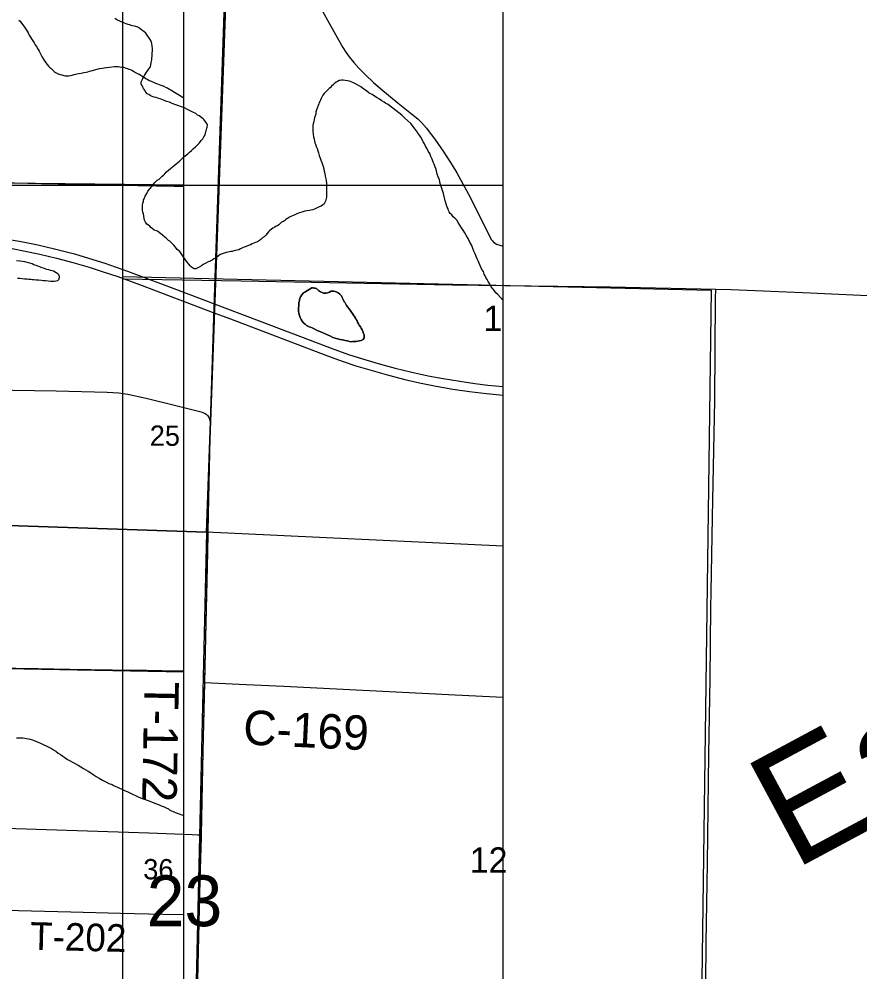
# Model space of a CAD drawing. Extents: x 0 to 68, y 0 to 52.9.
# Drawn here: x 49.292 to 51.122, y 35.551 to 37.625 of the extents above; entities that cross this region are included whole.
import ezdxf

# ---------------------------------------------------------------- set-up
doc = ezdxf.new("R2010")
doc.units = 0
for name, color, linetype in [('Default', 7, 'Continuous'), ('GM_X_County_Road', 7, 'Continuous'), ('GM_X_County_Road_Text', 7, 'Continuous'), ('GM_X_Minor_Lake', 7, 'Continuous'), ('GM_X_Minor_River', 7, 'Continuous'), ('GM_X_Minor_River_Text', 7, 'Continuous'), ('GM_X_State_Route', 7, 'Continuous'), ('GM_X_Township', 7, 'Continuous'), ('GM_X_Township_Road', 7, 'Continuous'), ('GM_X_Township_Road_Text', 7, 'Continuous')]:
    doc.layers.add(name, color=color, linetype=linetype)

msp = doc.modelspace()

# ---------------------------------------------------------------- linework, layer by layer
at = {"layer": 'Default'}
for p, q in [((49.5172, 34.4614), (49.5172, 52.9414)), ((50.3451, 32.7683), (50.3451, 42.0083)), ((49.6501, 31.1431), (49.6501, 38.5351)), ((41.1051, 37.2633), (50.3451, 37.2633))]:
    msp.add_line(p, q, dxfattribs=at)
for points in [[(48.4264, 37.8391), (49.7457, 37.7942), (49.6996, 36.5084), (48.3843, 36.5523)], [(48.3843, 36.5523), (49.6996, 36.5084), (49.6691, 35.1845), (48.3458, 35.227)]]:
    msp.add_lwpolyline(points, close=True, dxfattribs=at)
for points in [[(50.3451, 36.4776), (49.6996, 36.5084), (49.7457, 37.7942), (50.3451, 37.7786)], [(49.5419, 37.6098), (49.5384, 37.6108), (49.5354, 37.6113), (49.5324, 37.6123), (49.5289, 37.6133), (49.5244, 37.6149), (49.5214, 37.6164), (49.5179, 37.6179), (49.5139, 37.6194), (49.5094, 37.6214), (49.5059, 37.623), (49.5023, 37.625), (49.4998, 37.627)], [(49.5697, 37.2455), (49.5722, 37.2505), (49.5762, 37.2555), (49.5803, 37.261), (49.5868, 37.2695), (49.5923, 37.2745), (49.5964, 37.277), (49.6004, 37.28), (49.6034, 37.283), (49.6059, 37.2855), (49.6089, 37.2885), (49.6125, 37.2925), (49.6165, 37.296), (49.629, 37.3065), (49.6336, 37.31), (49.6371, 37.313), (49.6411, 37.316), (49.6436, 37.3185), (49.6466, 37.3215), (49.6502, 37.325), (49.6532, 37.3275), (49.6562, 37.3295), (49.6587, 37.332), (49.6617, 37.335), (49.6668, 37.339), (49.6708, 37.343), (49.6758, 37.347), (49.6798, 37.3515), (49.6844, 37.356), (49.6879, 37.3605), (49.6914, 37.3645), (49.6939, 37.369), (49.6959, 37.372), (49.6974, 37.3765), (49.698, 37.3795), (49.699, 37.382), (49.6995, 37.385), (49.7005, 37.3875), (49.701, 37.3901), (49.7015, 37.3941), (49.7, 37.3981), (49.698, 37.4011), (49.6945, 37.4056), (49.6925, 37.4081), (49.6895, 37.4102), (49.6865, 37.4122), (49.6835, 37.4142), (49.68, 37.4162), (49.676, 37.4197), (49.6695, 37.4228), (49.6639, 37.4253), (49.6579, 37.4283), (49.6514, 37.4319), (49.6309, 37.4394), (49.6248, 37.4415), (49.6188, 37.444), (49.6123, 37.446), (49.6063, 37.4486), (49.5988, 37.4516), (49.5938, 37.4531), (49.5898, 37.4541), (49.5857, 37.4551), (49.5812, 37.4567), (49.5772, 37.4587), (49.5737, 37.4607), (49.5707, 37.4627), (49.5672, 37.4662), (49.5647, 37.4713), (49.5627, 37.4738), (49.5612, 37.4768), (49.5592, 37.4803), (49.5577, 37.4833), (49.5577, 37.4883), (49.5597, 37.4928), (49.5607, 37.4959), (49.5628, 37.4994), (49.5648, 37.5024), (49.5668, 37.5059), (49.5688, 37.5094), (49.5718, 37.5134), (49.5743, 37.5169), (49.5774, 37.5209), (49.5784, 37.5254), (49.5794, 37.5309), (49.5799, 37.5339), (49.5804, 37.5364), (49.5809, 37.5404), (49.5814, 37.5455), (49.5814, 37.551), (49.582, 37.556), (49.582, 37.561), (49.5815, 37.566), (49.5805, 37.572), (49.5785, 37.5786), (49.5675, 37.5947), (49.5635, 37.5982), (49.559, 37.6012), (49.5545, 37.6047), (49.55, 37.6073), (49.546, 37.6088), (49.5419, 37.6098)], [(50.0654, 37.4571), (50.0599, 37.4611), (50.0539, 37.4642), (50.0479, 37.4687), (50.0419, 37.4727), (50.0354, 37.4778), (50.0253, 37.4838), (50.0178, 37.4873), (50.0108, 37.4899), (49.9973, 37.4924), (49.9932, 37.4919), (49.9907, 37.4914), (49.9882, 37.4915), (49.9847, 37.4895), (49.9817, 37.4875), (49.9792, 37.4855), (49.9757, 37.4825), (49.9716, 37.479), (49.9696, 37.4765), (49.9666, 37.474), (49.9641, 37.4715), (49.9616, 37.469), (49.9591, 37.4665), (49.9555, 37.463), (49.953, 37.4595), (49.9505, 37.4555), (49.949, 37.4525), (49.9475, 37.4489), (49.946, 37.4459), (49.945, 37.4434), (49.944, 37.4409), (49.9424, 37.4369), (49.9404, 37.4314), (49.9394, 37.4279), (49.9379, 37.4224), (49.9374, 37.4184), (49.9359, 37.4144), (49.9349, 37.4104), (49.9338, 37.4064), (49.9333, 37.4023), (49.9318, 37.3973), (49.9313, 37.3933), (49.9313, 37.3893), (49.9313, 37.3863), (49.9313, 37.3838), (49.9313, 37.3803), (49.9327, 37.3687), (49.9337, 37.3647), (49.9347, 37.3597), (49.9357, 37.3557), (49.9367, 37.3527), (49.9382, 37.3481), (49.9402, 37.3431), (49.9417, 37.3386), (49.9432, 37.3341), (49.9452, 37.3281), (49.9472, 37.3225), (49.9487, 37.318), (49.9507, 37.313), (49.9522, 37.3085), (49.9532, 37.304), (49.9547, 37.2994), (49.9557, 37.2939), (49.9571, 37.2889), (49.9581, 37.2834), (49.9591, 37.2773), (49.9601, 37.2728), (49.9606, 37.2678), (49.9611, 37.2638), (49.9611, 37.2588), (49.9611, 37.2538), (49.9611, 37.2487), (49.9606, 37.2447), (49.9611, 37.2417), (49.9605, 37.2377), (49.96, 37.2347), (49.9595, 37.2317), (49.9585, 37.2287), (49.957, 37.2262), (49.9555, 37.2232), (49.952, 37.2197), (49.949, 37.2182), (49.9449, 37.2162), (49.9404, 37.2142), (49.9359, 37.2122), (49.9314, 37.2102), (49.9269, 37.2092), (49.9238, 37.2087), (49.9183, 37.2077), (49.9138, 37.2068), (49.9093, 37.2058), (49.9002, 37.2028), (49.8962, 37.2013), (49.8917, 37.1993), (49.8867, 37.1968), (49.8832, 37.1953), (49.8802, 37.1938), (49.8756, 37.1908), (49.8726, 37.1888), (49.8691, 37.1858), (49.8656, 37.1838)], [(50.3451, 37.0128), (50.3338, 37.0253), (50.3298, 37.0293), (50.3263, 37.0334), (50.3238, 37.0369), (50.3213, 37.0394), (50.3188, 37.0434), (50.3173, 37.0464), (50.3158, 37.0494), (50.3128, 37.054), (50.3103, 37.058), (50.3078, 37.0625), (50.3063, 37.066), (50.3043, 37.0695), (50.3023, 37.0756), (50.2993, 37.0801), (50.2968, 37.0851), (50.2943, 37.0901), (50.2923, 37.0952), (50.2909, 37.0992), (50.2889, 37.1032), (50.2869, 37.1082), (50.2844, 37.1138), (50.2819, 37.1198), (50.2794, 37.1258), (50.2769, 37.1323), (50.2724, 37.1409), (50.2694, 37.1474), (50.2659, 37.1534), (50.2619, 37.1595), (50.2584, 37.1655), (50.2544, 37.171), (50.2509, 37.1766), (50.2474, 37.1821), (50.2444, 37.1876), (50.2404, 37.1917), (50.2369, 37.1947), (50.2339, 37.1987), (50.2299, 37.2022), (50.2279, 37.2057), (50.2264, 37.2083), (50.2254, 37.2118), (50.2234, 37.2158), (50.2219, 37.2203), (50.2204, 37.2248), (50.2194, 37.2293), (50.2154, 37.2454), (50.2124, 37.254), (50.2105, 37.2605), (50.2085, 37.2675), (50.2065, 37.275), (50.204, 37.2816), (50.202, 37.2876), (50.2, 37.2946), (50.1985, 37.3002), (50.1965, 37.3052), (50.195, 37.3092), (50.193, 37.3137), (50.191, 37.3202), (50.188, 37.3263), (50.1855, 37.3323), (50.1825, 37.3378), (50.1795, 37.3439), (50.1765, 37.3484), (50.174, 37.3534), (50.1715, 37.3579), (50.169, 37.363), (50.166, 37.368), (50.1631, 37.3725), (50.16, 37.377), (50.1565, 37.3816), (50.153, 37.3861), (50.1495, 37.3916), (50.1445, 37.3976), (50.138, 37.4037), (50.1315, 37.4097), (50.125, 37.4158), (50.118, 37.4208), (50.1115, 37.4258), (50.105, 37.4314), (50.0995, 37.4354), (50.095, 37.4394), (50.09, 37.4415), (50.086, 37.4445), (50.0814, 37.4475), (50.0764, 37.4505), (50.0714, 37.4536), (50.0654, 37.4571)], [(49.6501, 36.2035), (49.1852, 36.2124), (49.1976, 37.2693), (49.6501, 37.2645)], [(49.8656, 37.1838), (49.8631, 37.1828), (49.8601, 37.1798), (49.857, 37.1773), (49.854, 37.1753), (49.8515, 37.1744), (49.848, 37.1719), (49.844, 37.1699), (49.841, 37.1679), (49.8369, 37.1644), (49.8349, 37.1619), (49.8319, 37.1584), (49.8284, 37.1544), (49.8249, 37.1509), (49.8224, 37.1494), (49.8183, 37.1459), (49.8148, 37.1429), (49.8103, 37.1404), (49.8063, 37.1389), (49.8023, 37.1374), (49.7992, 37.1359), (49.7952, 37.1339), (49.7907, 37.1319), (49.7862, 37.1304), (49.7817, 37.1289), (49.7776, 37.1269), (49.7736, 37.1249), (49.7696, 37.123), (49.7656, 37.122), (49.7626, 37.1215), (49.7591, 37.1205), (49.7556, 37.1195), (49.7525, 37.119), (49.7495, 37.1185), (49.7465, 37.118), (49.7425, 37.117), (49.734, 37.114), (49.7294, 37.1125), (49.7249, 37.1091), (49.7224, 37.1071), (49.7194, 37.1046), (49.7159, 37.1031), (49.7119, 37.1006), (49.7093, 37.0991), (49.7068, 37.0976), (49.7033, 37.0966), (49.6983, 37.0941), (49.6953, 37.0926), (49.6923, 37.0911), (49.6888, 37.0881), (49.6837, 37.0851), (49.6792, 37.0826), (49.6762, 37.0816), (49.6727, 37.0816), (49.6692, 37.0836), (49.6667, 37.0852), (49.6637, 37.0877), (49.6612, 37.0917), (49.6577, 37.0957), (49.6542, 37.1008), (49.6502, 37.1063), (49.6462, 37.1123), (49.6417, 37.1189), (49.6356, 37.1234), (49.6321, 37.1284), (49.6281, 37.1329), (49.6246, 37.1365), (49.6216, 37.1395), (49.6196, 37.142), (49.6171, 37.1435), (49.6146, 37.1455), (49.6121, 37.148), (49.6086, 37.1506), (49.6036, 37.1546), (49.6001, 37.1576), (49.5971, 37.1601), (49.5926, 37.1632), (49.5881, 37.1652), (49.5851, 37.1662), (49.5816, 37.1692), (49.5786, 37.1712), (49.5761, 37.1742), (49.5731, 37.1768), (49.57, 37.1788), (49.5665, 37.1828), (49.5645, 37.1873), (49.5636, 37.1908), (49.5631, 37.1959), (49.5621, 37.2009), (49.5611, 37.2049), (49.5606, 37.2089), (49.5601, 37.2114), (49.5606, 37.2144), (49.5606, 37.2169), (49.5606, 37.2204), (49.5611, 37.2245), (49.5621, 37.228), (49.5626, 37.2315), (49.5637, 37.234), (49.5662, 37.2395), (49.5697, 37.2455)], [(49.5172, 37.0651), (50.798, 37.0352), (50.7632, 34.4614)]]:
    msp.add_lwpolyline(points, dxfattribs=at)
at = {"layer": 'GM_X_County_Road'}
for points in [[(49.5172, 37.06), (49.7752, 37.0553), (50.2346, 37.0466), (50.5792, 37.0423), (50.8081, 37.037)], [(50.8081, 37.037), (50.8417, 37.0362), (50.9975, 37.0302), (51.1859, 37.0214), (51.2351, 37.0199), (51.4672, 37.0095)], [(49.0484, 36.8262), (49.065, 36.8251), (49.1716, 36.8208), (49.2782, 36.8175), (49.3725, 36.8159), (49.4833, 36.8133), (49.5078, 36.8115), (49.5281, 36.8085), (49.5683, 36.8), (49.6359, 36.7831), (49.6878, 36.7704), (49.6954, 36.7674), (49.6989, 36.7651), (49.7018, 36.7624), (49.7043, 36.7588)], [(49.7043, 36.7588), (49.7064, 36.7539), (49.7076, 36.7476), (49.7078, 36.7352), (49.705, 36.6326), (49.7014, 36.4644), (49.6969, 36.247), (49.6952, 36.1873), (49.6951, 36.1812)], [(49.6951, 36.1812), (49.7105, 36.18), (49.7857, 36.1767), (49.8677, 36.1726), (50.2406, 36.1544), (50.3451, 36.1488)]]:
    msp.add_lwpolyline(points, dxfattribs=at)
at = {"layer": 'GM_X_Minor_Lake'}
for points in [[(49.2883, 37.0613), (49.2933, 37.0608), (49.2983, 37.0603), (49.3033, 37.0598), (49.3089, 37.0597), (49.3129, 37.0592), (49.3169, 37.0587), (49.3204, 37.0582), (49.3239, 37.0582), (49.3284, 37.0577), (49.3339, 37.0577), (49.3405, 37.0566), (49.345, 37.0561), (49.349, 37.0561), (49.3605, 37.0546), (49.3635, 37.0545), (49.3681, 37.0545), (49.3716, 37.055), (49.3756, 37.056), (49.3786, 37.059), (49.3796, 37.064), (49.3786, 37.0675), (49.3761, 37.0706), (49.3726, 37.0731), (49.3666, 37.0761), (49.3636, 37.0771), (49.3601, 37.0781), (49.3561, 37.0792), (49.3521, 37.0802), (49.348, 37.0817), (49.3445, 37.0832), (49.34, 37.0847), (49.3365, 37.0857), (49.3325, 37.0873), (49.3285, 37.0888), (49.324, 37.0903), (49.32, 37.0923), (49.315, 37.0938), (49.3094, 37.0954), (49.3039, 37.0964), (49.2989, 37.0974), (49.2934, 37.0979), (49.2859, 37.0989)], [(49.929, 37.0402), (49.9134, 37.0307), (49.9109, 37.0292), (49.9069, 37.0247), (49.9043, 37.0207), (49.9033, 37.0182), (49.9023, 37.0147), (49.9018, 37.0117), (49.9008, 37.0081), (49.9008, 37.0041), (49.9003, 37.0001), (49.8998, 36.9971), (49.8998, 36.9926), (49.8998, 36.9891), (49.9007, 36.9846), (49.9017, 36.9801), (49.9037, 36.9755), (49.9057, 36.971), (49.9082, 36.9675), (49.9107, 36.964), (49.9142, 36.961), (49.9172, 36.9584), (49.9202, 36.9569), (49.9228, 36.9554), (49.9258, 36.9544), (49.9298, 36.9529), (49.9343, 36.9509), (49.9393, 36.9483), (49.9443, 36.9458), (49.9498, 36.9433), (49.9694, 36.9347), (49.9749, 36.9317), (49.9794, 36.9306), (49.9849, 36.9291), (49.9904, 36.9276), (49.9954, 36.9266), (50.0015, 36.9256), (50.0065, 36.9245), (50.011, 36.9235), (50.015, 36.9225), (50.0185, 36.923), (50.0225, 36.923), (50.0255, 36.9235), (50.0285, 36.924), (50.0326, 36.9244), (50.0361, 36.9254), (50.0406, 36.9279)], [(49.929, 37.0402), (49.932, 37.0402), (49.934, 37.0396), (49.937, 37.0391), (49.9395, 37.0376), (49.9435, 37.0346), (49.9475, 37.0311), (49.9515, 37.0296), (49.9545, 37.0285), (49.9575, 37.0285), (49.9601, 37.0285), (49.9631, 37.029), (49.9671, 37.031), (49.9711, 37.0325), (49.9746, 37.0325), (49.9771, 37.0325), (49.9796, 37.032), (49.9821, 37.0315), (49.9861, 37.0289), (49.9897, 37.0264), (49.9932, 37.0224), (49.9952, 37.0189), (49.9961, 37.0164), (49.9996, 37.0098), (50.0011, 37.0073), (50.0046, 37.0013), (50.0121, 36.9912), (50.0146, 36.9877), (50.0171, 36.9842), (50.0196, 36.9807), (50.0216, 36.9777), (50.0236, 36.9741), (50.0256, 36.9711), (50.0276, 36.9686), (50.0286, 36.9656), (50.0306, 36.9616), (50.0321, 36.9591), (50.0346, 36.9555), (50.0366, 36.952), (50.0386, 36.9485), (50.0396, 36.946), (50.0416, 36.941), (50.0431, 36.9375), (50.0431, 36.9339), (50.0426, 36.9309), (50.0406, 36.9279), (50.0361, 36.9254), (50.0326, 36.9244), (50.0285, 36.924), (50.0255, 36.9235), (50.0225, 36.923), (50.0185, 36.923), (50.015, 36.9225), (50.011, 36.9235), (50.0065, 36.9245), (50.0015, 36.9256), (49.9954, 36.9266), (49.9904, 36.9276), (49.9849, 36.9291), (49.9794, 36.9306), (49.9749, 36.9317), (49.9694, 36.9347), (49.9498, 36.9433), (49.9443, 36.9458), (49.9393, 36.9483), (49.9343, 36.9509), (49.9298, 36.9529), (49.9258, 36.9544), (49.9228, 36.9554), (49.9202, 36.9569), (49.9172, 36.9584), (49.9142, 36.961), (49.9107, 36.964), (49.9082, 36.9675), (49.9057, 36.971), (49.9037, 36.9755), (49.9017, 36.9801), (49.9007, 36.9846), (49.8998, 36.9891), (49.8998, 36.9926), (49.8998, 36.9971), (49.9003, 37.0001), (49.9008, 37.0041), (49.9008, 37.0081), (49.9018, 37.0117), (49.9023, 37.0147), (49.9033, 37.0182), (49.9043, 37.0207), (49.9069, 37.0247), (49.9109, 37.0292), (49.9134, 37.0307), (49.929, 37.0402)], [(50.0406, 36.9279), (50.0426, 36.9309), (50.0431, 36.9339), (50.0431, 36.9375), (50.0416, 36.941), (50.0396, 36.946), (50.0386, 36.9485), (50.0366, 36.952), (50.0346, 36.9555), (50.0321, 36.9591), (50.0306, 36.9616), (50.0286, 36.9656), (50.0276, 36.9686), (50.0256, 36.9711), (50.0236, 36.9741), (50.0216, 36.9777), (50.0196, 36.9807), (50.0171, 36.9842), (50.0146, 36.9877), (50.0121, 36.9912), (50.0046, 37.0013), (50.0011, 37.0073), (49.9996, 37.0098), (49.9961, 37.0164), (49.9952, 37.0189), (49.9932, 37.0224), (49.9897, 37.0264), (49.9861, 37.0289), (49.9821, 37.0315), (49.9796, 37.032), (49.9771, 37.0325), (49.9746, 37.0325), (49.9711, 37.0325), (49.9671, 37.031), (49.9631, 37.029), (49.9601, 37.0285), (49.9575, 37.0285), (49.9545, 37.0285), (49.9515, 37.0296), (49.9475, 37.0311), (49.9435, 37.0346), (49.9395, 37.0376), (49.937, 37.0391), (49.934, 37.0396), (49.932, 37.0402), (49.929, 37.0402)]]:
    msp.add_lwpolyline(points, dxfattribs=at)
at = {"layer": 'GM_X_Minor_River'}
for points in [[(49.2913, 37.6229), (49.2937, 37.6205), (49.2957, 37.6184), (49.3032, 37.6079), (49.3063, 37.6034), (49.3091, 37.599), (49.3115, 37.5949), (49.3138, 37.5905), (49.3162, 37.586), (49.3186, 37.582), (49.3213, 37.5775), (49.3241, 37.5731), (49.3269, 37.5694), (49.3292, 37.5654), (49.3328, 37.5593), (49.3351, 37.5552), (49.3375, 37.5508), (49.3403, 37.5455), (49.3434, 37.5399), (49.3466, 37.5342), (49.3497, 37.5297), (49.3529, 37.5261), (49.3557, 37.5228), (49.3585, 37.52), (49.3609, 37.5183), (49.3636, 37.5155), (49.3664, 37.5122), (49.3688, 37.5106), (49.3712, 37.509), (49.3736, 37.5077), (49.3768, 37.5061), (49.3808, 37.5048), (49.3848, 37.5036), (49.3889, 37.5023), (49.3921, 37.5019), (49.3957, 37.5014), (49.4001, 37.5014), (49.4038, 37.5021), (49.407, 37.5029), (49.4114, 37.5044), (49.4171, 37.506), (49.4219, 37.5067), (49.4264, 37.5074), (49.4296, 37.5078), (49.4324, 37.5086), (49.4377, 37.5097), (49.4413, 37.5105), (49.4446, 37.5116), (49.4482, 37.5128), (49.4615, 37.5162), (49.4668, 37.5174), (49.4721, 37.5185), (49.4769, 37.5188), (49.4821, 37.5196), (49.4886, 37.5207), (49.4991, 37.5218), (49.5035, 37.5217), (49.5075, 37.5216), (49.5148, 37.5207), (49.5188, 37.5203), (49.5248, 37.5186), (49.5276, 37.5178), (49.5308, 37.5161), (49.5336, 37.5153), (49.5368, 37.5136), (49.5404, 37.5116), (49.5448, 37.5091), (49.5481, 37.5075), (49.5505, 37.5062)], [(49.5505, 37.5062), (49.5529, 37.505), (49.5565, 37.5029), (49.5588, 37.5013), (49.5621, 37.4996), (49.5652, 37.4976), (49.5692, 37.4951), (49.572, 37.4935), (49.5748, 37.4918), (49.5776, 37.4906), (49.5805, 37.4893), (49.5841, 37.4877), (49.5885, 37.486), (49.5929, 37.4844), (49.5965, 37.4827), (49.6001, 37.4811), (49.6065, 37.479), (49.6121, 37.4765), (49.6149, 37.4756), (49.6177, 37.4736), (49.6205, 37.4715), (49.6501, 37.4538)], [(49.2861, 36.0608), (49.2925, 36.0607), (49.2994, 36.0606), (49.3038, 36.0601), (49.3078, 36.0593), (49.3118, 36.0584), (49.3158, 36.0576), (49.3211, 36.0559), (49.3271, 36.0534), (49.3331, 36.0509), (49.3395, 36.048), (49.3455, 36.0455), (49.3507, 36.0431), (49.3563, 36.0398), (49.3623, 36.0373), (49.3667, 36.0344), (49.3715, 36.0311), (49.3763, 36.0274), (49.3815, 36.0242), (49.3867, 36.0209), (49.3915, 36.0176)], [(49.3915, 36.0176), (49.3971, 36.0135), (49.4027, 36.0102), (49.4075, 36.0078), (49.4123, 36.0053), (49.4199, 36.0008), (49.4263, 35.9971), (49.4319, 35.9938), (49.4371, 35.9909), (49.4423, 35.9876), (49.4479, 35.9843), (49.4531, 35.9806), (49.4594, 35.9765), (49.4662, 35.9724), (49.4734, 35.9683), (49.4802, 35.9646), (49.4867, 35.9613), (49.4939, 35.9588), (49.4987, 35.9563), (49.5043, 35.9538), (49.5207, 35.946), (49.5271, 35.9435), (49.5327, 35.941), (49.5387, 35.9377), (49.5451, 35.9352), (49.5511, 35.9323), (49.5596, 35.9286), (49.566, 35.9265), (49.5724, 35.924), (49.578, 35.9219), (49.5832, 35.9199), (49.5888, 35.9178), (49.5948, 35.9153), (49.6012, 35.9124), (49.6073, 35.9099), (49.6121, 35.9078), (49.6165, 35.9062), (49.6201, 35.9033), (49.6273, 35.9004), (49.6333, 35.8975), (49.6501, 35.8917)]]:
    msp.add_lwpolyline(points, dxfattribs=at)
at = {"layer": 'GM_X_State_Route'}
for points in [[(49.2559, 37.1478), (49.2964, 37.1408), (49.3326, 37.1335), (49.3687, 37.1252), (49.4125, 37.114), (49.443, 37.1049), (49.4781, 37.0937), (49.5277, 37.0766), (49.64, 37.0343), (49.7188, 37.0045), (49.9041, 36.9344), (49.977, 36.9067), (50.0112, 36.8946), (50.0468, 36.8834), (50.0787, 36.8741), (50.1104, 36.8655), (50.1463, 36.8567), (50.1824, 36.8488), (50.2147, 36.8426), (50.2511, 36.8366), (50.2836, 36.8319), (50.3122, 36.8285), (50.3451, 36.8254)], [(49.2763, 37.1258), (49.3047, 37.1201), (49.3367, 37.1134), (49.3733, 37.1048), (49.4083, 37.0956), (49.4443, 37.0853), (49.4749, 37.0751), (49.5062, 37.0645), (49.5536, 37.0471), (49.718, 36.985), (49.7515, 36.9723), (49.8525, 36.9339), (49.9629, 36.8921), (49.9974, 36.8794), (50.0246, 36.8704), (50.06, 36.8598), (50.0955, 36.8499), (50.1313, 36.8409), (50.1632, 36.8336), (50.1994, 36.8262), (50.2357, 36.8198), (50.2722, 36.8144), (50.3088, 36.8099), (50.3451, 36.8063)]]:
    msp.add_lwpolyline(points, dxfattribs=at)
at = {"layer": 'GM_X_Township'}
msp.add_lwpolyline([(44.7776, 37.9316), (45.7636, 37.9078), (45.7815, 37.9075), (46.4354, 37.887), (47.0934, 37.8749), (47.9758, 37.8521), (48.4292, 37.8378), (49.0919, 37.8129), (49.7424, 37.7891), (49.7157, 36.9972), (49.7077, 36.748), (49.6951, 36.1805), (49.6872, 35.8521), (49.6545, 34.5254), (49.6326, 33.8658), (49.6189, 33.2067), (49.6098, 32.7683)], dxfattribs=at)
at = {"layer": 'GM_X_Township_Road'}
for points in [[(49.9385, 37.6675), (49.984, 37.5848), (49.9962, 37.5635), (50.0028, 37.5532), (50.01, 37.5433), (50.0203, 37.5306), (50.0312, 37.5184), (50.0455, 37.5038), (50.0634, 37.4869), (50.0788, 37.4734), (50.1169, 37.4423), (50.1457, 37.4191), (50.1595, 37.4077), (50.1679, 37.4), (50.1785, 37.3879), (50.1802, 37.3858), (50.1968, 37.3634), (50.2161, 37.3356), (50.2345, 37.3068), (50.2446, 37.2903), (50.2743, 37.2358), (50.2934, 37.1979), (50.3175, 37.149), (50.3196, 37.1455), (50.3219, 37.1423), (50.3246, 37.1395), (50.3277, 37.1372), (50.3311, 37.1355), (50.3451, 37.131)], [(49.197, 37.2706), (49.2518, 37.2695), (49.3403, 37.2672), (49.4486, 37.2652), (49.488, 37.264), (49.5503, 37.2628), (49.629, 37.2611), (49.6501, 37.2607)], [(50.7869, 35.5244), (50.7876, 35.6147), (50.7905, 35.7869), (50.7935, 36.0247), (50.7957, 36.1887), (50.7978, 36.3445), (50.7981, 36.3773), (50.8008, 36.5412), (50.8059, 36.7954), (50.8079, 37.0168), (50.8081, 37.037)], [(49.1863, 36.2135), (49.3329, 36.2112), (49.4018, 36.2099), (49.5396, 36.208), (49.5692, 36.2077), (49.602, 36.207), (49.6501, 36.2063)], [(49.6951, 36.1812), (49.6944, 36.1606), (49.6912, 35.9962), (49.688, 35.8492)], [(48.3657, 35.894), (48.3969, 35.8934), (48.561, 35.8876), (48.7209, 35.8821), (48.8726, 35.8767), (49.0202, 35.8719), (49.217, 35.8654), (49.5738, 35.8534), (49.6681, 35.8501), (49.6804, 35.8495), (49.688, 35.8492)], [(49.688, 35.8492), (49.6879, 35.8446), (49.6849, 35.7504), (49.677, 35.4103), (49.6744, 35.3038), (49.6694, 35.0907), (49.663, 34.8695), (49.6534, 34.5335), (49.6531, 34.5245)], [(49.1838, 35.6879), (49.1905, 35.6876), (49.2036, 35.6869), (49.404, 35.6815), (49.5124, 35.6785), (49.6044, 35.6764), (49.6501, 35.6756)]]:
    msp.add_lwpolyline(points, dxfattribs=at)

# ---------------------------------------------------------------- texts
at = {"layer": 'Default'}
for s, height, p in [('1', 0.0553, (50.3023, 36.946)), ('25', 0.0442, (49.5761, 36.6962)), ('12', 0.05525, (50.2726, 35.7667)), ('36', 0.0442, (49.5619, 35.7524)), ('23', 0.1105, (49.5695, 35.6504))]:
    msp.add_text(s, height=height, rotation=0, dxfattribs=at).set_placement(p)
at = {"layer": 'GM_X_County_Road_Text'}
msp.add_text('C-169', height=0.075, rotation=357.2483, dxfattribs=at).set_placement((49.7782, 36.0463))
at = {"layer": 'GM_X_Minor_River_Text'}
msp.add_text('Eagle', height=0.25009, rotation=28.2145, dxfattribs=at).set_placement((50.9777, 35.7716))
at = {"layer": 'GM_X_Township_Road_Text'}
for s, height, rotation, p in [('T-172', 0.075, 268.8773, (49.5646, 36.1834)), ('T-202', 0.06, 358.5957, (49.3149, 35.5994))]:
    msp.add_text(s, height=height, rotation=rotation, dxfattribs=at).set_placement(p)

doc.saveas('drawing.dxf')
